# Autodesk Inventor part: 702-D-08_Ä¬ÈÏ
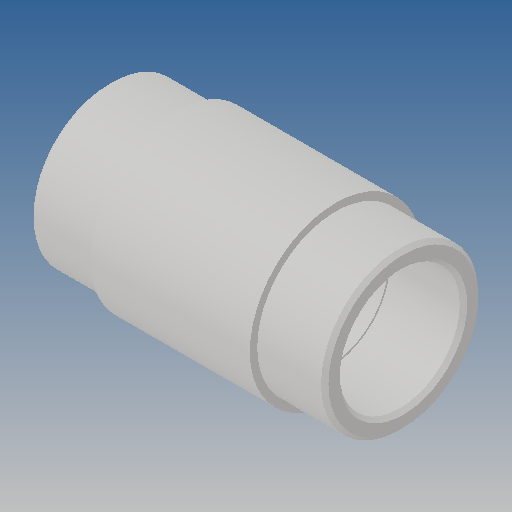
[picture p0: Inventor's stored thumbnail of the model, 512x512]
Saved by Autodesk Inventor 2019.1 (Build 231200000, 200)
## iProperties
Created: 2010-06
Part Number: 702-D-08_Ä¬ÈÏ
Material: Ogólny
Document SubType Name: Modeling
Designer: CADENGINEERING4
Density: 1 g/cm^3
Appearance: Domyślna
Author: CADENGINEERING4
Revision Number: ÈÎºÎ
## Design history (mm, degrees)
feature "NONE"
node "Bryła1"
